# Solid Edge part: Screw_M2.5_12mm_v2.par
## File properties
Author: Houman
Template: Normal.par
Last saved by: Houman
Revision: 12
Application: Solid Edge
Material: Stainless steel
Face Style: Steel
Fill Style: ANSI32(Steel)
Virtual Style: Stainless steel
Coef. of Thermal Exp: 1.6e-05
Thermal Conductivity: 17.0
Specific Heat: 502.0
Modulus of Elasticity: 193053196000.0
Poission's Ratio: 0.29
Yield Stress: 310264065.0
Ultimate Stress: 641212401.0
Elongation: 0.0
Density: 7750.000 kg/m^3
Accuracy: 0.990
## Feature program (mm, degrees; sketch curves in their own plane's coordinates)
body "unnamed Body 1"
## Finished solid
Body 1: solid body, 24 faces, 41 edges, 20 vertices.
  Faces by surface: plane 10, cone 9, cylinder 3, spline 2
  Edges by curve: circle 15, line 12, intersection 10, spline 4
Bounding box of the edges (mm; curved faces can reach further): 4.500 x 4.500 x 14.500, from (-2.25, -2.25, -14.5) to (2.25, 2.25, 0).
Cylindrical faces by radius (mm): R0.9577 x1, R1.25 x1, R2.25 x1
Conical faces (half-angle, radius in mm at the cone's reference point): 45 deg R1.1547 x6, 45 deg R2.025 x1, 45 deg R2.25 x1, 55 deg R0.7037 x1
Planar faces by outward normal: +x 1, +z 2, -x 1, -z 2, oblique 4
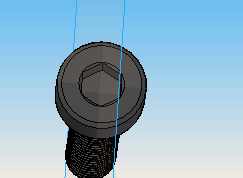
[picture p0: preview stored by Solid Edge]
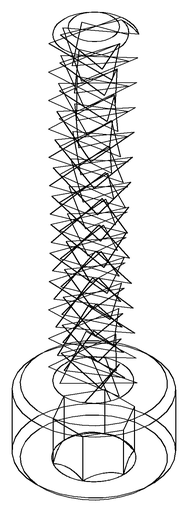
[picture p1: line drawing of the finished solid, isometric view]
